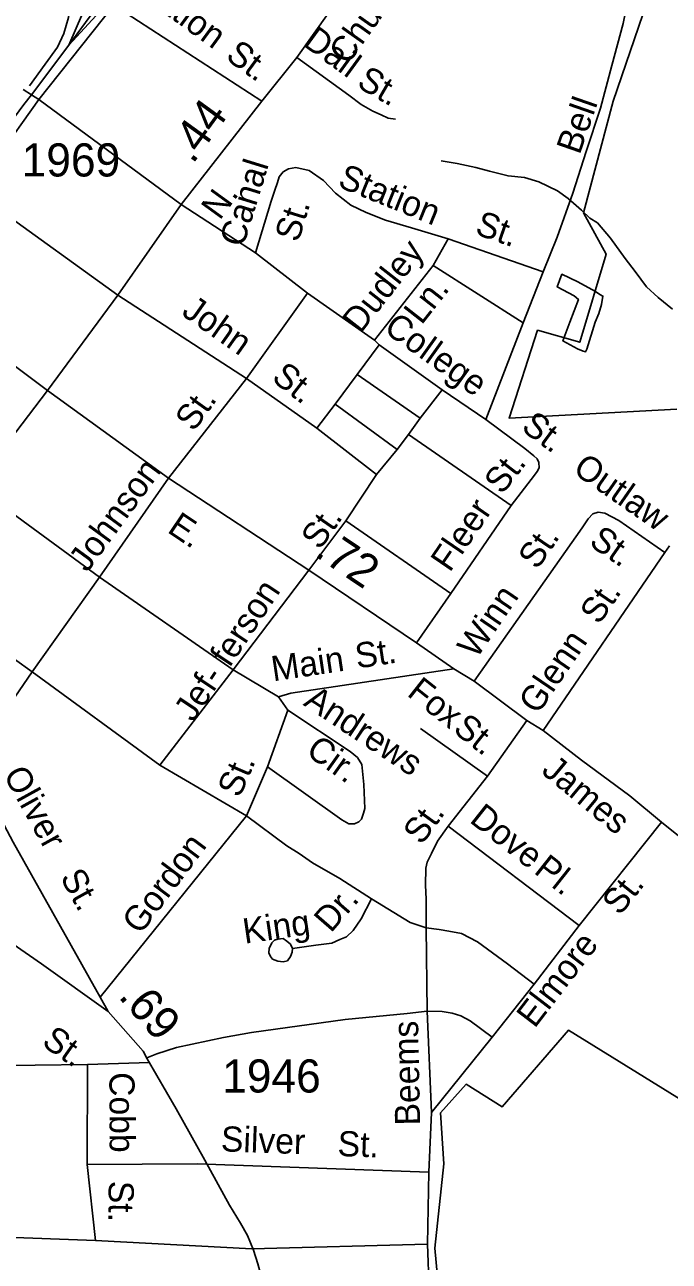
# Model space of a CAD drawing. Extents: x 2206922 to 2357709, y 510027 to 673830.
# Drawn here: x 2279424 to 2281854, y 524032 to 528698 of the extents above; entities that cross this region are included whole.
import ezdxf

# ---------------------------------------------------------------- set-up
doc = ezdxf.new("R2010")
doc.units = 0
for name, color, linetype in [('Exist Boundary Political City Limit New', 7, 'Continuous'), ('Exist Hydrographic Creek Single Shore', 7, 'Continuous'), ('Exist Hydrographic Misc Water Feature', 7, 'Continuous'), ('Exist Railroad Mainline', 7, 'Continuous'), ('Exist Railroad Siding', 7, 'Continuous'), ('Exist Road Non-System Type 51', 7, 'Continuous'), ('Exist Road Non-System Type 51 Label', 7, 'Continuous'), ('Exist Road Secondary Mileage Hundredths English Label', 7, 'Continuous'), ('Exist Road Secondary Type 51 Attributed', 7, 'Continuous'), ('Exist Road Secondary Type 51 Label', 7, 'Continuous'), ('Exist Road Secondary Type 51 Number Label', 7, 'Continuous'), ('Map Preparation Boundary City Limit Buffer Line', 7, 'Continuous')]:
    doc.layers.add(name, color=color, linetype=linetype)

msp = doc.modelspace()

# ---------------------------------------------------------------- linework, layer by layer
at = {"layer": 'Exist Boundary Political City Limit New'}
for points in [[(2281851.5, 529020.8), (2281643.2, 528409.9), (2281531, 527988.2), (2281616.2, 527832.1), (2281517, 527500.2), (2281358, 527545.6), (2281250.2, 527213.7), (2281882.8, 527247.7)], [(2282143.5, 524490.2), (2281474.5, 524904.4), (2281224.8, 524615), (2281088.8, 524700.1), (2280992.2, 524592.3), (2281003.8, 524399.4), (2280969.8, 524081.7), (2281012.8, 523620), (2281263.5, 523615.3), (2280984.2, 523436.8), (2280980, 523433.9), (2280978.8, 523433.1), (2280456, 523086), (2280353.5, 523018.8), (2279869.5, 523054.7), (2279270.8, 523083.8), (2278585.2, 523143.1), (2277873, 523183.1), (2277843.8, 522035.8), (2276722, 522886.9), (2276630.2, 522765.9), (2276555.2, 522661.6), (2276271.8, 522265.2), (2275788, 522640.8)]]:
    msp.add_lwpolyline(points, dxfattribs=at)
at = {"layer": 'Exist Hydrographic Creek Single Shore'}
msp.add_lwpolyline([(2280994, 528184.6), (2281053.9, 528174.7), (2281124.3, 528159), (2281176.3, 528145.2), (2281246.3, 528127.4), (2281308.4, 528121.6), (2281362.5, 528105.7), (2281432.7, 528072), (2281472.8, 528042.1), (2281523.1, 527998.2), (2281555.3, 527968.3), (2281583.2, 527950.4), (2281633.4, 527892.4), (2281687.9, 527816.6), (2281726.3, 527766.6), (2281768.5, 527708.7), (2281812.4, 527668.8), (2281866.7, 527624.9)], dxfattribs=at)
at = {"layer": 'Exist Hydrographic Misc Water Feature'}
msp.add_lwpolyline([(2281575, 527576), (2281543.8, 527473.9), (2281538, 527463.8), (2281530, 527465.8), (2281507.7, 527475.5), (2281453.6, 527505), (2281479, 527575.2), (2281512, 527661.4), (2281496, 527675.3), (2281431.8, 527708.7), (2281449.3, 527756.8), (2281509.5, 527727.4), (2281575.8, 527692.1), (2281592, 527680.2), (2281604.1, 527674.3), (2281598.3, 527642.3), (2281588.5, 527608.2), (2281575, 527576)], dxfattribs=at)
at = {"layer": 'Exist Railroad Mainline'}
for points in [[(2281467.1, 531188.9), (2281209, 530833.9), (2281173, 530784.4), (2280624.4, 530035.7), (2280515.8, 529886.7), (2280030.4, 529220.6), (2279590.3, 528620.7)], [(2279590.3, 528620.7), (2279448.4, 528434), (2279420.4, 528397.2), (2279196.7, 528094.8), (2279159.8, 528045), (2278937.9, 527743.7), (2278885.6, 527672.7), (2278669.6, 527377.5)]]:
    msp.add_lwpolyline(points, dxfattribs=at)
at = {"layer": 'Exist Railroad Siding'}
for points in [[(2281510.5, 531253.4), (2281439.9, 531112.7), (2281390.5, 531040.3), (2281238.3, 530833.9), (2281228.7, 530820.8), (2280972.2, 530470.7), (2280685.9, 530074.3), (2280536.6, 529874.6), (2280488.7, 529810.5), (2280216.2, 529442.2), (2279904.4, 529001.4), (2279693.1, 528733.6), (2279590.3, 528620.7)], [(2280422.6, 529807.9), (2280225.3, 529546.1), (2279937.2, 529149.7), (2279664.8, 528777.3), (2279641.1, 528741.2), (2279590.3, 528620.7)]]:
    msp.add_lwpolyline(points, dxfattribs=at)
at = {"layer": 'Exist Road Non-System Type 51'}
for p, q in [((2279476.3, 528415.6), (2279759, 528772.2)), ((2279759, 528772.2), (2280318, 528409.7)), ((2279417.8, 528454.3), (2279448.4, 528434)), ((2279476.3, 528415.6), (2279229.2, 528070.9)), ((2279448.4, 528434), (2279476.3, 528415.6)), ((2279476.3, 528415.6), (2280013.9, 528020)), ((2279229.2, 528070.9), (2279774.5, 527678.3)), ((2280293.3, 527837.9), (2280013.9, 528020)), ((2280963.5, 527790.2), (2281020.5, 527890.6)), ((2281020.5, 527890.6), (2281379.4, 527766)), ((2280293.3, 527837.9), (2280490.5, 527685.8)), ((2280742.1, 527508.2), (2280963.5, 527790.2)), ((2280963.5, 527790.2), (2281303.2, 527573.4)), ((2281379.4, 527766), (2281303.2, 527573.4)), ((2279508.8, 527318.1), (2278958.8, 527729.3)), ((2279774.5, 527678.3), (2280259.7, 527363.7)), ((2280490.5, 527685.8), (2280259.7, 527363.7)), ((2280742.1, 527508.2), (2280490.5, 527685.8)), ((2281303.2, 527573.4), (2281162.7, 527208.2)), ((2280760.3, 527490.4), (2280742.1, 527508.2)), ((2280760.3, 527490.4), (2280677.5, 527377.7)), ((2280760.3, 527490.4), (2280997.8, 527320.7)), ((2280677.5, 527377.7), (2280594.5, 527266.8)), ((2280677.5, 527377.7), (2280914.9, 527214)), ((2280259.7, 527363.7), (2279966, 526987.5)), ((2280259.7, 527363.7), (2280525.5, 527176.3)), ((2280914.9, 527214), (2280997.8, 527320.7)), ((2281162.7, 527208.2), (2280997.8, 527320.7)), ((2280594.5, 527266.8), (2280525.5, 527176.3)), ((2280594.5, 527266.8), (2280827.9, 527095.2)), ((2280871.4, 527151.5), (2280914.9, 527214)), ((2280525.5, 527176.3), (2280750.8, 527000.6)), ((2280827.9, 527095.2), (2280871.4, 527151.5)), ((2281257.7, 526883.4), (2280871.4, 527151.5)), ((2280750.8, 527000.6), (2280827.9, 527095.2)), ((2280750.8, 527000.6), (2280634.6, 526825.6)), ((2279235.3, 526958), (2279704.9, 526613.4)), ((2279704.9, 526613.4), (2279966, 526987.5)), ((2281030.9, 526551.3), (2281257.7, 526883.4)), ((2280634.6, 526825.6), (2280494.5, 526640.3)), ((2280634.6, 526825.6), (2281030.9, 526551.3)), ((2281837.1, 526706.8), (2281855.9, 526731.2)), ((2281837.1, 526706.8), (2281378.8, 526035.4)), ((2280210, 526263.8), (2280494.5, 526640.3)), ((2278974.3, 526596.3), (2279451.6, 526256.4)), ((2279451.6, 526256.4), (2279704.9, 526613.4)), ((2279704.9, 526613.4), (2280210, 526263.8)), ((2281030.9, 526551.3), (2280900.8, 526366.2)), ((2279451.6, 526256.4), (2279210.6, 525905.5)), ((2279933.6, 525903.9), (2279451.6, 526256.4)), ((2280210, 526263.8), (2279933.6, 525903.9)), ((2280380.9, 526161.6), (2280210, 526263.8)), ((2280415.5, 526111.9), (2280380.9, 526161.6)), ((2280339.6, 525897.3), (2280415.5, 526111.9)), ((2281317, 526072.8), (2281169.4, 525863)), ((2280916.2, 526043), (2281169.4, 525863)), ((2279933.6, 525903.9), (2280259.3, 525712.6)), ((2280259.3, 525712.6), (2280339.6, 525897.3)), ((2281169.4, 525863), (2281020.1, 525673.9)), ((2280259.3, 525712.6), (2279707.5, 525028.4)), ((2281514.5, 525298.7), (2281824.7, 525689.3)), ((2281020.1, 525673.9), (2281514.5, 525298.7)), ((2280941.1, 524975.5), (2280937.8, 525289.7)), ((2281514.5, 525298.7), (2281344.7, 525077.3)), ((2281344.7, 525077.3), (2281186.6, 524877.9)), ((2279738.4, 524974.8), (2279707.5, 525028.4)), ((2280957.5, 524593.9), (2280941.1, 524975.5)), ((2281186.6, 524877.9), (2280957.5, 524593.9)), ((2279659.1, 524397.8), (2279660.2, 524774.9)), ((2279660.2, 524774.9), (2279893.5, 524782.4)), ((2280957.5, 524593.9), (2280947.6, 524368)), ((2280074.2, 524399.8), (2279659.1, 524397.8)), ((2279659.1, 524397.8), (2279690.7, 524110.2)), ((2280947.6, 524368), (2280074.2, 524399.8)), ((2280942.1, 524096), (2280947.6, 524368)), ((2278546.5, 524151.5), (2279690.7, 524110.2)), ((2279690.7, 524110.2), (2280279.6, 524078.5)), ((2280279.6, 524078.5), (2280942.1, 524096)), ((2280942.1, 524096), (2280949.9, 523906.3))]:
    msp.add_line(p, q, dxfattribs=at)
for points in [[(2281379.4, 527766), (2281432, 527896.5), (2281490.5, 528062.9), (2281541.1, 528219.2), (2281595.4, 528383.6), (2281638, 528544.1), (2281680.3, 528702.4), (2281720.5, 528900.5), (2281754.7, 529088.7), (2281769.8, 529192.8), (2281771.3, 529238.9)], [(2280450.2, 528574.8), (2280645.5, 528432.7), (2280691.8, 528397.2), (2280736, 528371.5), (2280768.1, 528357.9), (2280794.3, 528346.2), (2280822.2, 528342.4)], [(2280293.3, 527837.9), (2280353.3, 528032.2), (2280367, 528074.3), (2280376.7, 528102.5), (2280382.6, 528124.4), (2280398.3, 528142.6), (2280418.2, 528154.8), (2280446.1, 528159.1), (2280496.2, 528147.5), (2280550.6, 528110), (2280595.1, 528062.5), (2280653.3, 528017.1), (2280711.6, 527989.6), (2280783.9, 527960.3), (2280882.1, 527931.2), (2281020.5, 527890.6)], [(2281257.7, 526883.4), (2281346.6, 526998.2), (2281356.5, 527012.2), (2281364.3, 527026.2), (2281362.1, 527046.3), (2281356, 527060.2), (2281343.9, 527072), (2281309.6, 527099.7), (2281162.7, 527208.2)], [(2281118.4, 526221.1), (2281526.3, 526799.9), (2281548, 526834.2), (2281566, 526852.2), (2281585.9, 526858.4), (2281611.8, 526854.7), (2281664, 526827.3), (2281837.1, 526706.8)], [(2280380.9, 526161.6), (2280426.8, 526176.1), (2281041.6, 526267.6)], [(2280415.5, 526111.9), (2280650.9, 525956.2), (2280679, 525932.5), (2280695.2, 525906.6), (2280701.9, 525830.6), (2280706.7, 525740.8), (2280700.9, 525722.7), (2280693.1, 525700.7), (2280683.3, 525690.7), (2280667.4, 525682.4), (2280645.4, 525682.2), (2280619.3, 525698), (2280339.6, 525897.3)], [(2279210.6, 525905.5), (2279255.4, 525846.8), (2279380, 525613.2), (2279707.5, 525028.4)], [(2280259.3, 525712.6), (2280412.2, 525600.2), (2280458.6, 525570.8), (2280508.8, 525535.1), (2280611.4, 525476), (2280731.7, 525399.5)], [(2280937.8, 525289.7), (2280937, 525398.9), (2280935.6, 525450.7), (2280936.3, 525515.5), (2280941.3, 525538.6), (2280957.2, 525570.3), (2280980.2, 525617.8), (2281020.1, 525673.9)], [(2280731.7, 525399.5), (2280691.8, 525324.7), (2280661.9, 525279.8), (2280637.4, 525256.4), (2280611.4, 525246.4), (2280581.7, 525231.9), (2280521.8, 525225.4), (2280434, 525212.5)], [(2280731.7, 525399.5), (2280876.8, 525310.8), (2280937.8, 525289.7)], [(2280937.8, 525289.7), (2280987, 525283.7), (2281022.9, 525278.1), (2281071.1, 525268.5), (2281131.2, 525237), (2281244.1, 525154.2), (2281344.7, 525077.3)], [(2280434, 525212.5), (2280432.1, 525198.5), (2280426.2, 525182.5), (2280414.3, 525166.4), (2280398.4, 525162.3), (2280378.4, 525164), (2280358.4, 525171.8), (2280350.2, 525181.8), (2280344.1, 525195.8), (2280346, 525211.7), (2280355.6, 525233.9), (2280365.6, 525243.9), (2280377.5, 525248.1), (2280397.6, 525250.2), (2280411.5, 525240.4), (2280425.7, 525228.5), (2280434, 525212.5)], [(2280941.1, 524975.5), (2280866.1, 524966.7), (2280632.3, 524944.6), (2280279.1, 524895.4), (2280173.1, 524876.4), (2279995.6, 524838.8), (2279921.1, 524814.8), (2279883.6, 524800)], [(2280941.1, 524975.5), (2280997.8, 524974), (2281035.8, 524968.3), (2281068, 524958.7), (2281104, 524939.2), (2281186.6, 524877.9)], [(2278523.2, 524755.4), (2279263.7, 524769.8), (2279660.2, 524774.9)]]:
    msp.add_lwpolyline(points, dxfattribs=at)
at = {"layer": 'Exist Road Secondary Type 51 Attributed'}
msp.add_line((2279508.8, 527318.1), (2279235.3, 526958), dxfattribs=at)
for points in [[(2279134.3, 529685.5), (2279475.8, 529438.7), (2279799.5, 529209.1), (2279638.5, 528987.8), (2279628.8, 528952.9), (2279613, 528907.2), (2279602, 528850.4), (2279595.7, 528784.2), (2279588.6, 528725), (2279571.2, 528665.1), (2279547.6, 528613), (2279500.2, 528550), (2279441.9, 528467.1)], [(2279508.8, 527318.1), (2279774.5, 527678.3), (2280013.9, 528020), (2280318, 528409.7), (2280450.2, 528574.8), (2280888.3, 529192.5)], [(2283200.6, 524854.5), (2283048.4, 524936.7), (2282912.5, 525013.9), (2282715.6, 525118.1), (2282627, 525164.7), (2282570.6, 525192.9), (2282434.3, 525263.5), (2282331.9, 525322.5), (2282259.6, 525365.8), (2282179, 525422.9), (2282046.1, 525517.5), (2281921.3, 525612.4), (2281824.7, 525689.3), (2281705.9, 525788.3), (2281523.5, 525923), (2281378.8, 526035.4), (2281317, 526072.8), (2281118.4, 526221.1), (2281041.6, 526267.6), (2280900.8, 526366.2), (2280494.5, 526640.3), (2279966, 526987.5), (2279508.8, 527318.1)], [(2278449, 525885.3), (2278947.5, 525530.3), (2279193.6, 525357.1), (2279486.1, 525154.1), (2279738.4, 524974.8), (2279870.4, 524825.1), (2279885.8, 524795.8), (2279994.7, 524607.2), (2280102.2, 524413), (2280196, 524243.4), (2280237.6, 524175.6), (2280263.1, 524129.1), (2280286.5, 524073.6), (2280303.2, 524021.9), (2280332.6, 523913), (2280370.2, 523773.3), (2280399.6, 523650.4), (2280413.5, 523541.4), (2280414.9, 523481.3), (2280413.5, 523405.9), (2280419.1, 523270.4), (2280421.9, 523225.7), (2280424.7, 523122.3), (2280424.7, 523065.4)]]:
    msp.add_lwpolyline(points, dxfattribs=at)
at = {"layer": 'Map Preparation Boundary City Limit Buffer Line'}
for points in [[(2281851.5, 529020.8), (2281643.2, 528409.9), (2281531, 527988.2), (2281616.2, 527832.1), (2281517, 527500.2), (2281358, 527545.6), (2281250.2, 527213.7), (2281882.8, 527247.7)], [(2282143.5, 524490.2), (2281474.5, 524904.4), (2281224.8, 524615), (2281088.8, 524700.1), (2280992.2, 524592.3), (2281003.8, 524399.4), (2280969.8, 524081.7), (2281012.8, 523620), (2281263.5, 523615.3), (2280984.2, 523436.8), (2280980, 523433.9), (2280978.8, 523433.1), (2280456, 523086), (2280353.5, 523018.8), (2279869.5, 523054.7), (2279270.8, 523083.8), (2278585.2, 523143.1), (2277873, 523183.1), (2277843.8, 522035.8), (2276722, 522886.9), (2276630.2, 522765.9), (2276555.2, 522661.6), (2276271.8, 522265.2), (2275788, 522640.8)]]:
    msp.add_lwpolyline(points, dxfattribs=at)

# ---------------------------------------------------------------- texts
at = {"layer": 'Exist Road Non-System Type 51 Label'}
for s, rotation, p in [('Station', 323.7815, (2279817.9, 528837)), ('Dail', 323.9603, (2280468.2, 528622.6)), ('St.', 323.7815, (2280176.9, 528571.1)), ('St.', 329.8219, (2280671.6, 528465.9)), ('Bell', 70.8218, (2281516.3, 528204.6)), ('Canal', 72.8394, (2280247.1, 527854.9)), ('Station', 337.9409, (2280599.7, 528088.1)), ('St.', 72.8394, (2280455.4, 527874.1)), ('St.', 340.8545, (2281117.8, 527909)), ('Dudley', 51.864, (2280689, 527528.7)), ('Ln.', 51.864, (2280920.2, 527562.5)), ('John', 324.8145, (2280010.8, 527605.3)), ('College', 324.4535, (2280773.2, 527541.7)), ('St.', 322.051, (2280350.4, 527358.2)), ('St.', 54.3769, (2280061, 527158.9)), ('St.', 323.5503, (2281291.8, 527170.4)), ('Johnson', 53.8233, (2279659.2, 526628.5)), ('St.', 52.2458, (2281224, 526921.8)), ('Outlaw', 325.1574, (2281486.4, 527009.7)), ('Fleer', 55.6696, (2281026.7, 526628.5)), ('St.', 55.1617, (2280537, 526712.7)), ('St.', 55.6847, (2281356.5, 526638.5)), ('St.', 325.1574, (2281547.7, 526736.4)), ('Jef- ferson', 56.4157, (2280059.1, 526063.2)), ('Winn', 55.6847, (2281127.1, 526302.3)), ('St.', 55.734, (2281589.6, 526430.8)), ('Glenn', 55.734, (2281358.6, 526091.8)), ('Main', 8.4651, (2280360.5, 526220.3)), ('St.', 8.4651, (2280676.9, 526268.7)), ('Fox', 321.6886, (2280861.4, 526169.1)), ('Andrews', 326.5185, (2280470.8, 526132)), ('St.', 321.6886, (2281034.7, 526032.2)), ('Cir.', 324.5287, (2280479.3, 525946.5)), ('Oliver', 298.9281, (2279341, 525868.5)), ('St.', 66.5027, (2280233.9, 525777.5)), ('St.', 54.0228, (2280920.4, 525599.4)), ('Dove', 321.6489, (2281097.1, 525691.8)), ('Gordon', 53.1569, (2279859.5, 525261.1)), ('Pl.', 321.6489, (2281340, 525499.6)), ('St.', 298.9281, (2279555.1, 525481.1)), ('St.', 51.5447, (2281667.9, 525333)), ('Dr.', 49.0466, (2280578.1, 525268.2)), ('King', 8.2955, (2280253, 525230.1)), ('Elmore', 52.5265, (2281346.5, 524908)), ('Beems', 91.1933, (2280915.1, 524545.3)), ('Cobb', 270.231, (2279742.7, 524745.5)), ('Silver', 357.8834, (2280162.2, 524447.2)), ('St.', 357.8834, (2280602.2, 524429.5)), ('St.', 269.7234, (2279740, 524335.8))]:
    msp.add_text(s, height=95, rotation=rotation, dxfattribs=at).set_placement(p)
at = {"layer": 'Exist Road Secondary Mileage Hundredths English Label'}
for s, rotation, p in [('.44', 54.0425, (2280057.1, 528169.5)), ('.72', 325.9953, (2280512.2, 526695.8)), ('.69', 311.3975, (2279773.5, 525029.6))]:
    msp.add_text(s, height=125, rotation=rotation, dxfattribs=at).set_placement(p)
at = {"layer": 'Exist Road Secondary Type 51 Label'}
for s, rotation, p in [('Church', 54.654, (2280641.3, 528542.9)), ('N.', 54.0425, (2280159.2, 527957.4)), ('E.', 325.9953, (2279957, 526785.8)), ('James', 320.3261, (2281368.1, 525876.4)), ('St.', 324.8987, (2279483.1, 524849.6))]:
    msp.add_text(s, height=95, rotation=rotation, dxfattribs=at).set_placement(p)
at = {"layer": 'Exist Road Secondary Type 51 Number Label'}
for s, p in [('1969', (2279411.8, 528125.5)), ('1946', (2280168.2, 524668.8))]:
    msp.add_text(s, height=125, dxfattribs=at).set_placement(p)

doc.saveas('drawing.dxf')
